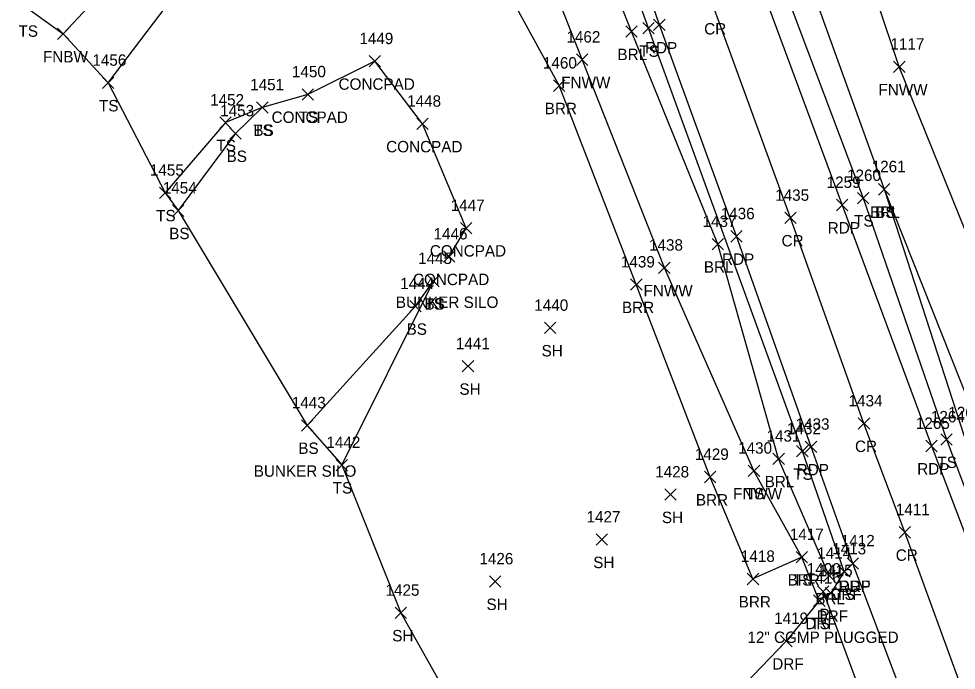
# Model space of a CAD drawing. Extents: x 1443590 to 1445966, y 578314 to 580556.
# Drawn here: x 1445184.7 to 1445349.1, y 578567.5 to 578681.7 of the extents above; entities that cross this region are included whole.
import ezdxf

# ---------------------------------------------------------------- set-up
doc = ezdxf.new("R2010")
doc.units = 0
for name, color, linetype in [('D_A', 7, 'Continuous'), ('D_C', 7, 'Continuous'), ('D_I', 7, 'Continuous'), ('D_TIC', 7, 'Continuous'), ('DCP', 7, 'Continuous'), ('L_A', 7, 'Continuous'), ('L_C', 7, 'Continuous'), ('L_I', 7, 'Continuous'), ('L_TIC', 7, 'Continuous'), ('LABL', 7, 'Continuous'), ('LELB', 7, 'Continuous'), ('LFNC', 7, 'Continuous'), ('LS', 7, 'Continuous'), ('LSOGP', 7, 'Continuous'), ('P_A', 7, 'Continuous'), ('P_I', 7, 'Continuous'), ('P_TIC', 7, 'Continuous'), ('PET', 7, 'Continuous'), ('PRC', 7, 'Continuous'), ('R_A', 7, 'Continuous'), ('R_I', 7, 'Continuous'), ('R_TIC', 7, 'Continuous'), ('RDF', 7, 'Continuous')]:
    doc.layers.add(name, color=color, linetype=linetype)

msp = doc.modelspace()

# ---------------------------------------------------------------- linework, layer by layer
at = {"layer": 'D_TIC'}
for points in [[(1445324.76, 578580.28), (1445326.76, 578582.28)], [(1445326.76, 578580.28), (1445324.76, 578582.28)]]:
    msp.add_lwpolyline(points, dxfattribs=at)
at = {"layer": 'DCP'}
msp.add_lwpolyline([(1445325.76, 578581.28), (1445337.51, 578549.52)], dxfattribs=at)
at = {"layer": 'L_TIC'}
for points in [[(1445191.51, 578678.04), (1445193.51, 578680.04)], [(1445193.51, 578678.04), (1445191.51, 578680.04)], [(1445291.17, 578678.45), (1445293.17, 578680.45)], [(1445293.17, 578678.45), (1445291.17, 578680.45)], [(1445294.15, 578679.03), (1445296.15, 578681.03)], [(1445296.15, 578679.03), (1445294.15, 578681.03)], [(1445246.17, 578673.25), (1445248.17, 578675.25)], [(1445248.17, 578673.25), (1445246.17, 578675.25)], [(1445282.5, 578673.53), (1445284.5, 578675.53)], [(1445284.5, 578673.53), (1445282.5, 578675.53)], [(1445338.12, 578672.28), (1445340.12, 578674.28)], [(1445340.12, 578672.28), (1445338.12, 578674.28)], [(1445199.4, 578669.46), (1445201.4, 578671.46)], [(1445201.4, 578669.46), (1445199.4, 578671.46)], [(1445278.47, 578668.97), (1445280.47, 578670.97)], [(1445280.47, 578668.97), (1445278.47, 578670.97)], [(1445234.42, 578667.44), (1445236.42, 578669.44)], [(1445236.42, 578667.44), (1445234.42, 578669.44)], [(1445234.42, 578667.44), (1445236.42, 578669.44)], [(1445236.42, 578667.44), (1445234.42, 578669.44)], [(1445226.44, 578665.16), (1445228.44, 578667.16)], [(1445228.44, 578665.16), (1445226.44, 578667.16)], [(1445226.44, 578665.16), (1445228.44, 578667.16)], [(1445228.44, 578665.16), (1445226.44, 578667.16)], [(1445219.99, 578662.49), (1445221.99, 578664.49)], [(1445221.99, 578662.49), (1445219.99, 578664.49)], [(1445254.52, 578662.28), (1445256.52, 578664.28)], [(1445256.52, 578662.28), (1445254.52, 578664.28)], [(1445221.74, 578660.59), (1445223.74, 578662.59)], [(1445223.74, 578660.59), (1445221.74, 578662.59)], [(1445209.42, 578650.19), (1445211.42, 578652.19)], [(1445211.42, 578650.19), (1445209.42, 578652.19)], [(1445335.45, 578650.8), (1445337.45, 578652.8)], [(1445337.45, 578650.8), (1445335.45, 578652.8)], [(1445335.45, 578650.8), (1445337.45, 578652.8)], [(1445337.45, 578650.8), (1445335.45, 578652.8)], [(1445331.79, 578649.27), (1445333.79, 578651.27)], [(1445333.79, 578649.27), (1445331.79, 578651.27)], [(1445211.68, 578647.06), (1445213.68, 578649.06)], [(1445213.68, 578647.06), (1445211.68, 578649.06)], [(1445262.16, 578644.01), (1445264.16, 578646.01)], [(1445264.16, 578644.01), (1445262.16, 578646.01)], [(1445306.32, 578641.19), (1445308.32, 578643.19)], [(1445308.32, 578641.19), (1445306.32, 578643.19)], [(1445259.22, 578639.01), (1445261.22, 578641.01)], [(1445261.22, 578639.01), (1445259.22, 578641.01)], [(1445296.93, 578637.05), (1445298.93, 578639.05)], [(1445298.93, 578637.05), (1445296.93, 578639.05)], [(1445256.44, 578634.71), (1445258.44, 578636.71)], [(1445258.44, 578634.71), (1445256.44, 578636.71)], [(1445256.44, 578634.71), (1445258.44, 578636.71)], [(1445258.44, 578634.71), (1445256.44, 578636.71)], [(1445292.01, 578634.1), (1445294.01, 578636.1)], [(1445294.01, 578634.1), (1445292.01, 578636.1)], [(1445253.3, 578630.3), (1445255.3, 578632.3)], [(1445255.3, 578630.3), (1445253.3, 578632.3)], [(1445276.91, 578626.51), (1445278.91, 578628.51)], [(1445278.91, 578626.51), (1445276.91, 578628.51)], [(1445262.51, 578619.78), (1445264.51, 578621.78)], [(1445264.51, 578619.78), (1445262.51, 578621.78)], [(1445234.3, 578609.42), (1445236.3, 578611.42)], [(1445236.3, 578609.42), (1445234.3, 578611.42)], [(1445346.4, 578606.95), (1445348.4, 578608.95)], [(1445348.4, 578606.95), (1445346.4, 578608.95)], [(1445321.12, 578604.88), (1445323.12, 578606.88)], [(1445323.12, 578604.88), (1445321.12, 578606.88)], [(1445240.37, 578602.47), (1445242.37, 578604.47)], [(1445242.37, 578602.47), (1445240.37, 578604.47)], [(1445316.97, 578603.57), (1445318.97, 578605.57)], [(1445318.97, 578603.57), (1445316.97, 578605.57)], [(1445312.64, 578601.46), (1445314.64, 578603.46)], [(1445314.64, 578601.46), (1445312.64, 578603.46)], [(1445312.64, 578601.46), (1445314.64, 578603.46)], [(1445314.64, 578601.46), (1445312.64, 578603.46)], [(1445304.97, 578600.37), (1445306.97, 578602.37)], [(1445306.97, 578600.37), (1445304.97, 578602.37)], [(1445298.01, 578597.29), (1445300.01, 578599.29)], [(1445300.01, 578597.29), (1445298.01, 578599.29)], [(1445285.97, 578589.4), (1445287.97, 578591.4)], [(1445287.97, 578589.4), (1445285.97, 578591.4)], [(1445321.05, 578586.33), (1445323.05, 578588.33)], [(1445323.05, 578586.33), (1445321.05, 578588.33)], [(1445321.05, 578586.33), (1445323.05, 578588.33)], [(1445323.05, 578586.33), (1445321.05, 578588.33)], [(1445312.47, 578582.5), (1445314.47, 578584.5)], [(1445314.47, 578582.5), (1445312.47, 578584.5)], [(1445325.85, 578583.05), (1445327.85, 578585.05)], [(1445327.85, 578583.05), (1445325.85, 578585.05)], [(1445328.48, 578583.81), (1445330.48, 578585.81)], [(1445330.48, 578583.81), (1445328.48, 578585.81)], [(1445267.25, 578582.06), (1445269.25, 578584.06)], [(1445269.25, 578582.06), (1445267.25, 578584.06)], [(1445324.1, 578578.69), (1445326.1, 578580.69)], [(1445326.1, 578578.69), (1445324.1, 578580.69)], [(1445250.74, 578576.56), (1445252.74, 578578.56)], [(1445252.74, 578576.56), (1445250.74, 578578.56)]]:
    msp.add_lwpolyline(points, dxfattribs=at)
at = {"layer": 'LABL'}
for points in [[(1445292.63, 578789.9), (1445288, 578780.72), (1445303.45, 578740.92), (1445320.45, 578696.23), (1445336.45, 578651.8), (1445353.16, 578609.77), (1445368.17, 578573), (1445383.72, 578526.34), (1445398.46, 578486.57), (1445412.31, 578451.09), (1445415.12, 578445.83), (1445420.11, 578428.88), (1445425.31, 578411.87), (1445435.24, 578381.31), (1445438.11, 578382.76), (1445447.54, 578352.71)], [(1445326.85, 578584.05), (1445317.97, 578604.57), (1445307.32, 578642.19), (1445292.17, 578679.45), (1445280.08, 578709.69), (1445269.47, 578721.91), (1445260.6, 578716.61)], [(1445322.05, 578587.33), (1445313.47, 578583.5), (1445305.97, 578601.37), (1445293.01, 578635.1), (1445279.47, 578669.97), (1445266.59, 578693.66), (1445260.6, 578716.61)]]:
    msp.add_lwpolyline(points, dxfattribs=at)
at = {"layer": 'LELB'}
for points in [[(1445329.48, 578584.81), (1445322.12, 578605.88), (1445295.15, 578680.03), (1445283.74, 578711.72), (1445273.93, 578731.48), (1445266.49, 578750.22), (1445265.68, 578752.11), (1445264.69, 578763.32), (1445260.56, 578773.29), (1445259.58, 578775.95), (1445258.32, 578778.63), (1445255.83, 578784.34), (1445248.03, 578805.63), (1445228.29, 578856.25), (1445216.45, 578887.34), (1445198.29, 578930.27), (1445196.84, 578934.05), (1445190.79, 578941.35), (1445189.32, 578948.18), (1445182.47, 578967.95), (1445172.93, 578988.88)], [(1445222.69, 578937.93), (1445234.28, 578911.39), (1445254.78, 578861.13), (1445268.94, 578819.8), (1445281.41, 578785.26), (1445283.41, 578779.74), (1445299.6, 578739.58), (1445316.15, 578694.47), (1445332.79, 578650.27), (1445347.4, 578607.95), (1445361.62, 578570.36), (1445377.25, 578524), (1445391.22, 578483.59), (1445406.36, 578442.9), (1445418.34, 578410.04), (1445429.91, 578378.9), (1445440.4, 578350.18)], [(1445200.4, 578670.46), (1445212.83, 578686.8), (1445223.68, 578699.88), (1445241.17, 578720.13), (1445257.25, 578739.36), (1445265.68, 578752.11)], [(1445235.42, 578668.44), (1445227.44, 578666.16), (1445220.99, 578663.49), (1445210.42, 578651.19)], [(1445227.44, 578666.16), (1445222.74, 578661.59), (1445212.68, 578648.06)], [(1445336.45, 578651.8), (1445350.45, 578608.68), (1445364.47, 578571.58), (1445379.66, 578524.91), (1445393.71, 578484.47), (1445409.17, 578449.94), (1445411.12, 578445.67), (1445411.54, 578444.09), (1445413.6, 578439.47), (1445415.72, 578428.29), (1445422.38, 578411.18), (1445431.91, 578379.51), (1445442.14, 578350.66)], [(1445235.3, 578610.42), (1445254.3, 578631.3), (1445257.44, 578635.71)], [(1445241.37, 578603.47), (1445257.44, 578635.71)], [(1445325.1, 578579.69), (1445322.05, 578587.33), (1445313.64, 578602.46)]]:
    msp.add_lwpolyline(points, dxfattribs=at)
at = {"layer": 'LFNC'}
for points in [[(1445192.51, 578679.04), (1445204.62, 578692.01), (1445226.1, 578714.33), (1445242.47, 578733.97), (1445254.41, 578746.23), (1445250.78, 578767.41), (1445249.79, 578770.3), (1445248.54, 578772.3), (1445247.12, 578775.95), (1445233.63, 578799.84), (1445217.34, 578852.45), (1445204.74, 578883.21), (1445203.98, 578884.28)], [(1445459.96, 578349.35), (1445445.8, 578387.44), (1445435.66, 578413.46), (1445430.43, 578428.44), (1445420.82, 578457.49), (1445411.95, 578480.76), (1445399.21, 578511.56), (1445382.81, 578556.03), (1445370.45, 578591.65), (1445354.37, 578635.55), (1445339.12, 578673.28), (1445323.48, 578719.9), (1445315.49, 578748.71)], [(1445313.64, 578602.46), (1445297.93, 578638.05), (1445283.5, 578674.53), (1445273.1, 578700.91)]]:
    msp.add_lwpolyline(points, dxfattribs=at)
at = {"layer": 'LS'}
msp.add_lwpolyline([(1445260.22, 578640.01), (1445263.16, 578645.01), (1445255.52, 578663.28), (1445247.17, 578674.25), (1445235.42, 578668.44)], dxfattribs=at)
at = {"layer": 'LSOGP'}
msp.add_lwpolyline([(1445179.36, 578688.65), (1445186.3, 578683.55), (1445192.51, 578679.04), (1445200.4, 578670.46), (1445210.42, 578651.2), (1445212.69, 578648.07), (1445235.3, 578610.43), (1445241.38, 578603.48), (1445251.74, 578577.57), (1445268.47, 578547.81)], dxfattribs=at)
at = {"layer": 'P_TIC'}
for points in [[(1445296.05, 578679.63), (1445298.05, 578681.63)], [(1445298.05, 578679.63), (1445296.05, 578681.63)], [(1445328.09, 578648.05), (1445330.09, 578650.05)], [(1445330.09, 578648.05), (1445328.09, 578650.05)], [(1445319.05, 578645.79), (1445321.05, 578647.79)], [(1445321.05, 578645.79), (1445319.05, 578647.79)], [(1445309.56, 578642.56), (1445311.56, 578644.56)], [(1445311.56, 578642.56), (1445309.56, 578644.56)], [(1445331.93, 578609.75), (1445333.93, 578611.75)], [(1445333.93, 578609.75), (1445331.93, 578611.75)], [(1445322.64, 578605.66), (1445324.64, 578607.66)], [(1445324.64, 578605.66), (1445322.64, 578607.66)], [(1445343.77, 578605.81), (1445345.77, 578607.81)], [(1445345.77, 578605.81), (1445343.77, 578607.81)], [(1445339.07, 578590.68), (1445341.07, 578592.68)], [(1445341.07, 578590.68), (1445339.07, 578592.68)], [(1445329.99, 578585.22), (1445331.99, 578587.22)], [(1445331.99, 578585.22), (1445329.99, 578587.22)]]:
    msp.add_lwpolyline(points, dxfattribs=at)
at = {"layer": 'PET'}
for points in [[(1445418.89, 578342.02), (1445405.88, 578377.14), (1445393.26, 578414.23), (1445384.94, 578436.64), (1445373.41, 578468.96), (1445357.56, 578512.83), (1445344.62, 578550.03), (1445330.99, 578586.22), (1445323.64, 578606.66), (1445310.56, 578643.56), (1445297.05, 578680.63), (1445286.07, 578712.45), (1445276.51, 578732.61), (1445268.43, 578753.25), (1445256.91, 578785.04), (1445249.61, 578806.41), (1445230.56, 578857.31), (1445217.97, 578888.99), (1445200.05, 578931.7), (1445199.72, 578935.44), (1445193.89, 578943.66), (1445183.72, 578968.31), (1445171.41, 579000.64)], [(1445204.47, 578977.72), (1445211.07, 578960.69), (1445220.5, 578936.98), (1445230.76, 578910.15), (1445251.08, 578859.52), (1445265.4, 578819.79), (1445279.28, 578781.46), (1445295.62, 578738.27), (1445312.78, 578693.03), (1445329.09, 578649.05), (1445344.77, 578606.81), (1445359.16, 578569.06), (1445375.47, 578523.38), (1445389.92, 578483.27), (1445404.56, 578441.9), (1445416.57, 578409.56), (1445427.35, 578377.72), (1445437.94, 578349.1)]]:
    msp.add_lwpolyline(points, dxfattribs=at)
at = {"layer": 'PRC'}
msp.add_lwpolyline([(1445428.76, 578345.92), (1445416.12, 578381.06), (1445402.82, 578417.2), (1445394.53, 578440.03), (1445382.79, 578472.56), (1445367.55, 578515.78), (1445354.3, 578552.77), (1445340.07, 578591.68), (1445332.93, 578610.75), (1445320.05, 578646.79), (1445306.48, 578683.94), (1445294.78, 578715.83), (1445285.68, 578740.23), (1445278.69, 578759.19), (1445266.72, 578790.29), (1445259.42, 578810.95), (1445240.14, 578861.33), (1445228.56, 578891.21), (1445209.9, 578937.12), (1445195.27, 578973.7), (1445179.73, 579007.4), (1445167.09, 579032.9), (1445157.85, 579050.89), (1445142.74, 579080.19)], dxfattribs=at)
at = {"layer": 'R_TIC'}
for points in [[(1445329.99, 578585.22), (1445331.99, 578587.22)], [(1445331.99, 578585.22), (1445329.99, 578587.22)], [(1445328.48, 578583.81), (1445330.48, 578585.81)], [(1445330.48, 578583.81), (1445328.48, 578585.81)], [(1445326.1, 578579.99), (1445328.1, 578581.99)], [(1445328.1, 578579.99), (1445326.1, 578581.99)], [(1445324.1, 578578.69), (1445326.1, 578580.69)], [(1445326.1, 578578.69), (1445324.1, 578580.69)], [(1445318.31, 578571.61), (1445320.31, 578573.61)], [(1445320.31, 578571.61), (1445318.31, 578573.61)]]:
    msp.add_lwpolyline(points, dxfattribs=at)
at = {"layer": 'RDF'}
msp.add_lwpolyline([(1445330.99, 578586.22), (1445329.48, 578584.81), (1445327.1, 578580.99), (1445325.1, 578579.69), (1445319.31, 578572.61), (1445306.28, 578559.03), (1445292.56, 578549.16), (1445271.42, 578539.22)], dxfattribs=at)

# ---------------------------------------------------------------- texts
at = {"layer": 'D_A'}
msp.add_text('P', height=2, dxfattribs=at).set_placement((1445325.14, 578576.28))
at = {"layer": 'D_C'}
msp.add_text('12" CGMP PLUGGED', height=2, dxfattribs=at).set_placement((1445312.49, 578572.28))
at = {"layer": 'D_I'}
msp.add_text('1400', height=2, dxfattribs=at).set_placement((1445322.9, 578584.28))
at = {"layer": 'L_A'}
for s, p in [('TS', (1445184.7, 578678.54)), ('BRL', (1445289.71, 578674.45)), ('TS', (1445293.55, 578675.03)), ('FNBW', (1445188.99, 578674.04)), ('FNWW', (1445279.85, 578669.53)), ('CONCPAD', (1445240.81, 578669.25)), ('FNWW', (1445335.47, 578668.28)), ('TS', (1445198.81, 578665.46)), ('BRR', (1445276.96, 578664.97)), ('CONCPAD', (1445229.07, 578663.44)), ('TS', (1445233.83, 578663.44)), ('TS', (1445225.85, 578661.16)), ('BS', (1445225.88, 578661.16)), ('TS', (1445219.4, 578658.49)), ('CONCPAD', (1445249.16, 578658.28)), ('BS', (1445221.18, 578656.59)), ('BRL', (1445333.99, 578646.8)), ('BS', (1445334.89, 578646.8)), ('TS', (1445208.83, 578646.19)), ('TS', (1445331.2, 578645.27)), ('BS', (1445211.12, 578643.06)), ('CONCPAD', (1445256.81, 578640.01)), ('BRL', (1445304.86, 578637.19)), ('CONCPAD', (1445253.86, 578635.01)), ('FNWW', (1445294.28, 578633.05)), ('TS', (1445255.85, 578630.71)), ('BS', (1445255.88, 578630.71)), ('BRR', (1445290.5, 578630.1)), ('BS', (1445252.74, 578626.3)), ('SH', (1445276.4, 578622.51)), ('SH', (1445262, 578615.78)), ('BS', (1445233.75, 578605.42)), ('TS', (1445345.81, 578602.95)), ('TS', (1445320.53, 578600.88)), ('BRL', (1445315.51, 578599.57)), ('TS', (1445239.78, 578598.47)), ('FNWW', (1445309.98, 578597.46)), ('TS', (1445312.05, 578597.46)), ('BRR', (1445303.46, 578596.37)), ('SH', (1445297.5, 578593.29)), ('SH', (1445285.46, 578585.4)), ('BRR', (1445319.54, 578582.33)), ('TS', (1445320.46, 578582.33)), ('BRL', (1445324.39, 578579.05)), ('TS', (1445327.89, 578579.81)), ('SH', (1445266.74, 578578.06)), ('BRR', (1445310.96, 578578.5)), ('TS', (1445323.51, 578574.69)), ('SH', (1445250.22, 578572.56))]:
    msp.add_text(s, height=2, dxfattribs=at).set_placement(p)
at = {"layer": 'L_C'}
for p in [(1445250.85, 578631.01), (1445225.94, 578601.42)]:
    msp.add_text('BUNKER SILO', height=2, dxfattribs=at).set_placement(p)
at = {"layer": 'L_I'}
for s, p in [('1449', (1445244.46, 578677.25)), ('1462', (1445280.76, 578677.53)), ('1117', (1445337.56, 578676.28)), ('1456', (1445197.65, 578673.46)), ('1460', (1445276.64, 578672.97)), ('1450', (1445232.64, 578671.44)), ('1450', (1445232.64, 578671.44)), ('1451', (1445225.31, 578669.16)), ('1451', (1445225.31, 578669.16)), ('1452', (1445218.29, 578666.49)), ('1448', (1445252.83, 578666.28)), ('1453', (1445220.05, 578664.59)), ('1261', (1445334.28, 578654.8)), ('1261', (1445334.28, 578654.8)), ('1455', (1445207.73, 578654.19)), ('1260', (1445329.96, 578653.27)), ('1454', (1445209.99, 578651.06)), ('1447', (1445260.47, 578648.01)), ('1437', (1445304.62, 578645.19)), ('1446', (1445257.47, 578643.01)), ('1438', (1445295.24, 578641.05)), ('1445', (1445254.75, 578638.71)), ('1445', (1445254.75, 578638.71)), ('1439', (1445290.31, 578638.1)), ('1444', (1445251.61, 578634.3)), ('1440', (1445275.13, 578630.51)), ('1441', (1445261.38, 578623.78)), ('1443', (1445232.61, 578613.42)), ('1264', (1445344.66, 578610.95)), ('1263', (1445347.71, 578611.68)), ('1432', (1445319.43, 578608.88)), ('1431', (1445315.84, 578607.57)), ('1442', (1445238.68, 578606.47)), ('1430', (1445310.86, 578605.46)), ('1430', (1445310.86, 578605.46)), ('1429', (1445303.27, 578604.37)), ('1428', (1445296.32, 578601.29)), ('1427', (1445284.28, 578593.4)), ('1417', (1445319.92, 578590.33)), ('1417', (1445319.92, 578590.33)), ('1413', (1445327.36, 578587.81)), ('1426', (1445265.5, 578586.06)), ('1418', (1445311.35, 578586.5)), ('1414', (1445324.73, 578587.05)), ('1416', (1445322.92, 578582.69)), ('1425', (1445249.04, 578580.56))]:
    msp.add_text(s, height=2, dxfattribs=at).set_placement(p)
at = {"layer": 'P_A'}
for s, p in [('CR', (1445304.91, 578678.94)), ('RDP', (1445294.54, 578675.63)), ('RDP', (1445326.57, 578644.05)), ('CR', (1445318.48, 578641.79)), ('RDP', (1445308.04, 578638.56)), ('CR', (1445331.36, 578605.75)), ('RDP', (1445321.13, 578601.66)), ('RDP', (1445342.26, 578601.81)), ('CR', (1445338.5, 578586.68)), ('RDP', (1445328.47, 578581.22))]:
    msp.add_text(s, height=2, dxfattribs=at).set_placement(p)
at = {"layer": 'P_I'}
for s, p in [('1259', (1445326.38, 578652.05)), ('1435', (1445317.36, 578649.79)), ('1436', (1445307.81, 578646.56)), ('1434', (1445330.23, 578613.75)), ('1433', (1445320.94, 578609.66)), ('1265', (1445342.03, 578609.81)), ('1411', (1445338.51, 578594.68)), ('1412', (1445328.86, 578589.22))]:
    msp.add_text(s, height=2, dxfattribs=at).set_placement(p)
at = {"layer": 'R_A'}
for p in [(1445328.52, 578581.22), (1445327.02, 578579.81), (1445324.64, 578575.99), (1445322.64, 578574.69), (1445316.85, 578567.61)]:
    msp.add_text('DRF', height=2, dxfattribs=at).set_placement(p)
at = {"layer": 'R_I'}
for s, p in [('1412', (1445328.86, 578589.22)), ('1413', (1445327.36, 578587.81)), ('1415', (1445324.98, 578583.99)), ('1416', (1445322.92, 578582.69)), ('1419', (1445317.18, 578575.61))]:
    msp.add_text(s, height=2, dxfattribs=at).set_placement(p)

doc.saveas('drawing.dxf')
